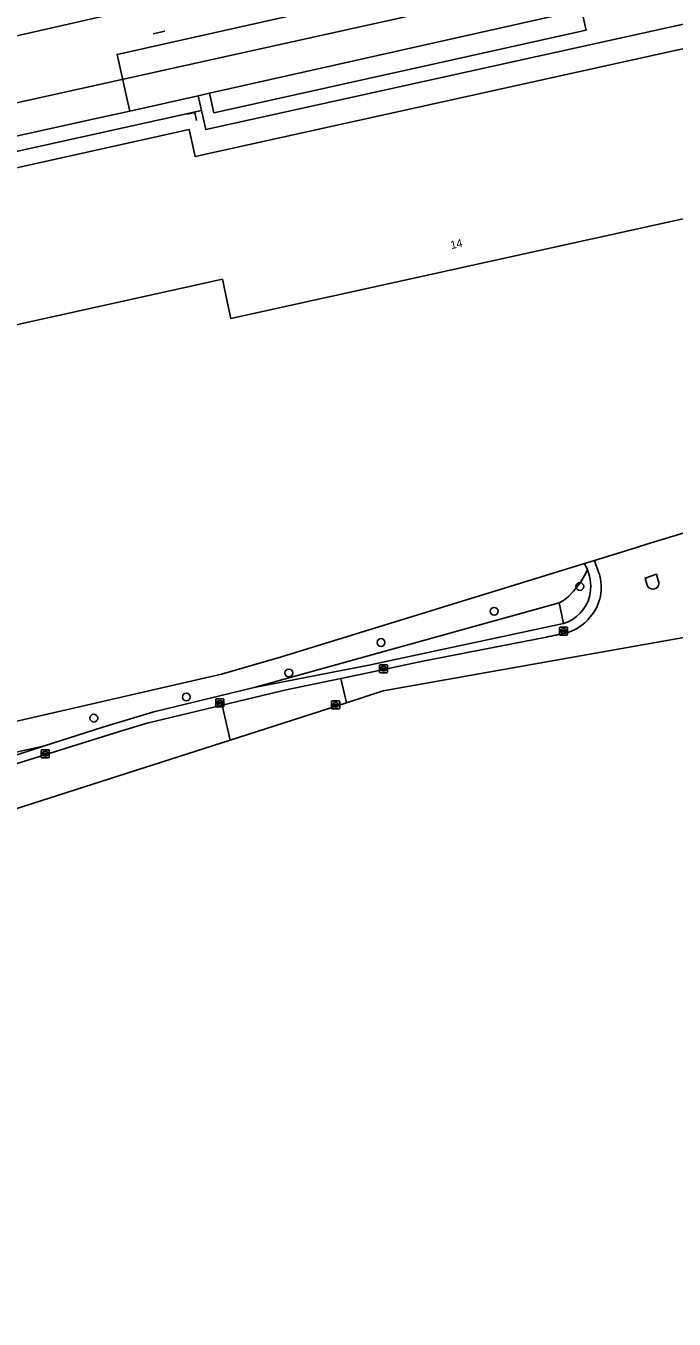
# Model space of a CAD drawing. Extents: x 161477 to 163040, y 383680 to 384871.
# Drawn here: x 162229.1 to 162310.1, y 383720.1 to 383881.8 of the extents above; entities that cross this region are included whole.
import ezdxf

# ---------------------------------------------------------------- set-up
doc = ezdxf.new("R2010")
doc.units = 0
for name, color, linetype in [('IMGEO_Boom', 7, 'Continuous'), ('IMGEO_Erf', 7, 'Continuous'), ('IMGEO_Groenvoorziening', 7, 'Continuous'), ('IMGEO_Hek', 7, 'Continuous'), ('IMGEO_Kolk', 7, 'Continuous'), ('IMGEO_Muur', 7, 'Continuous'), ('IMGEO_Overkapping', 7, 'Continuous'), ('IMGEO_Pand', 7, 'Continuous'), ('IMGEO_Pand_nummerreeks', 7, 'Continuous'), ('IMGEO_Rijbaan_lokaal_open', 7, 'Continuous'), ('IMGEO_Rioolput', 7, 'Continuous'), ('IMGEO_Spoor', 7, 'Continuous'), ('IMGEO_Spoorbaan_halfverhard', 7, 'Continuous'), ('IMGEO_Terreindeel_gesloten', 7, 'Continuous'), ('IMGEO_Terreindeel_halfverhard', 7, 'Continuous'), ('IMGEO_Verkeerseiland_gesloten', 7, 'Continuous'), ('IMGEO_Voetpad_open', 7, 'Continuous')]:
    doc.layers.add(name, color=color, linetype=linetype)

msp = doc.modelspace()

# ---------------------------------------------------------------- linework, layer by layer
at = {"layer": 'IMGEO_Boom'}
for centre in [(162298.35, 383811.69), (162287.64, 383808.59), (162273.51, 383804.69), (162261.99, 383800.88), (162249.18, 383797.87), (162237.62, 383795.23)]:
    msp.add_circle(centre, 0.489, dxfattribs=at)
at = {"layer": 'IMGEO_Erf'}
for points in [[(162421.56, 383883.57), (162312.05, 383859.38), (162312.37, 383857.91), (162254.76, 383845.19), (162254.46, 383846.53), (162253.68, 383850.09), (162222.78, 383843.26)], [(161913.96, 383727.2), (162034.23, 383752.62), (162061.02, 383757.62), (162072.88, 383760.06), (162200.21, 383788.99), (162215.71, 383792.24), (162226.94, 383794.59), (162253.58, 383800.74), (162261.09, 383802.89), (162298.92, 383814.56), (162300.16, 383814.95), (162305.42, 383816.57), (162306.83, 383817), (162311.78, 383818.53), (162312.56, 383818.77), (162312.8, 383817.2), (162313.95, 383815.04), (162315.67, 383812.77), (162316.14, 383812.14)]]:
    msp.add_lwpolyline(points, dxfattribs=at)
at = {"layer": 'IMGEO_Groenvoorziening'}
for points in [[(162298.92, 383814.56), (162261.09, 383802.89), (162253.58, 383800.74), (162226.94, 383794.59), (162215.71, 383792.24), (162200.21, 383788.99), (162072.88, 383760.06), (162061.02, 383757.62), (162034.23, 383752.62), (161913.96, 383727.2)], [(162216.7, 383788.57), (162231.35, 383791.72), (162238.76, 383794.1), (162245.14, 383796.02), (162257.67, 383799.06), (162295.76, 383809.64), (162296.29, 383809.94), (162296.93, 383810.45), (162297.55, 383811.11), (162298.41, 383812.2), (162298.92, 383813.07), (162299.3, 383813.78)], [(162299.3, 383813.78), (162298.92, 383813.07), (162298.41, 383812.2), (162297.55, 383811.11), (162296.93, 383810.45), (162296.29, 383809.94), (162295.76, 383809.64), (162296.32, 383807.07)], [(162007.91, 383740.73), (162033.22, 383746.19), (162060.49, 383752.12), (162097.3, 383759.98), (162118.07, 383764.45), (162141.54, 383769.48), (162180.49, 383777.87), (162190.22, 383779.97), (162198.07, 383781.8), (162206.11, 383783.95), (162214.63, 383786.44), (162216.75, 383787.01), (162217.08, 383787.12), (162231.35, 383791.72), (162216.7, 383788.57), (162197.76, 383783.49), (162191.42, 383781.95), (162037.84, 383749.41), (161933.79, 383726.48)]]:
    msp.add_lwpolyline(points, dxfattribs=at)
msp.add_lwpolyline([(162295.76, 383809.64), (162257.67, 383799.06), (162272.19, 383801.91), (162296.32, 383807.07)], close=True, dxfattribs=at)
for centre, radius, start, end in [((162293.81, 383811.61), 5.89, 21.5643, 30.0357), ((162293.93, 383811.67), 5.77, 347.7831, 21.4277), ((162294.88, 383811.7), 4.85, 287.2964, 345.1082)]:
    msp.add_arc(centre, radius, start, end, dxfattribs=at)
at = {"layer": 'IMGEO_Hek'}
for points in [[(162245.02, 383880.76), (162246.5, 383881.08)], [(162215.71, 383792.24), (162226.94, 383794.59), (162253.58, 383800.74), (162261.09, 383802.89), (162298.92, 383814.56)]]:
    msp.add_lwpolyline(points, dxfattribs=at)
at = {"layer": 'IMGEO_Kolk'}
for p, q in [((162295.82, 383805.68), (162295.82, 383806.54)), ((162295.9, 383806.61), (162296.75, 383806.61)), ((162296.08, 383806.1), (162296.08, 383806.12)), ((162296.52, 383806.07), (162296.12, 383806.07)), ((162296.13, 383806.15), (162296.52, 383806.15)), ((162296.31, 383806.39), (162296.34, 383806.39)), ((162296.57, 383806.12), (162296.57, 383806.1)), ((162296.82, 383806.54), (162296.82, 383805.68)), ((162296.75, 383805.61), (162295.9, 383805.61)), ((162296.33, 383805.83), (162296.31, 383805.83)), ((162273.3, 383800.99), (162273.3, 383801.84)), ((162273.38, 383801.91), (162274.23, 383801.91)), ((162273.56, 383801.41), (162273.56, 383801.42)), ((162273.6, 383801.46), (162274, 383801.46)), ((162274, 383801.37), (162273.6, 383801.37)), ((162273.79, 383801.69), (162273.81, 383801.69)), ((162273.81, 383801.13), (162273.79, 383801.13)), ((162274.04, 383801.42), (162274.04, 383801.41)), ((162274.3, 383801.84), (162274.3, 383800.99)), ((162274.23, 383800.91), (162273.38, 383800.91)), ((162252.86, 383796.71), (162252.86, 383797.56)), ((162252.93, 383797.64), (162253.79, 383797.64)), ((162253.79, 383796.64), (162252.93, 383796.64)), ((162253.12, 383797.13), (162253.12, 383797.14)), ((162253.16, 383797.18), (162253.56, 383797.18)), ((162253.56, 383797.09), (162253.16, 383797.09)), ((162253.35, 383797.42), (162253.37, 383797.42)), ((162253.37, 383796.86), (162253.35, 383796.86)), ((162253.6, 383797.14), (162253.6, 383797.13)), ((162253.86, 383797.56), (162253.86, 383796.71)), ((162231.06, 383790.36), (162231.06, 383791.21)), ((162231.13, 383791.29), (162231.98, 383791.29)), ((162231.98, 383790.28), (162231.13, 383790.28)), ((162231.31, 383790.78), (162231.31, 383790.79)), ((162231.75, 383790.74), (162231.35, 383790.74)), ((162231.36, 383790.83), (162231.75, 383790.83)), ((162231.54, 383791.06), (162231.57, 383791.06)), ((162231.57, 383790.51), (162231.54, 383790.51)), ((162231.8, 383790.79), (162231.8, 383790.78)), ((162232.06, 383791.21), (162232.06, 383790.36))]:
    msp.add_line(p, q, dxfattribs=at)
for points in [[(162295.82, 383805.68), (162295.82, 383806.54)], [(162295.9, 383806.61), (162296.75, 383806.61)], [(162296.82, 383806.54), (162296.82, 383805.68)], [(162296.75, 383805.61), (162295.9, 383805.61)], [(162273.3, 383800.99), (162273.3, 383801.84)], [(162273.38, 383801.91), (162274.23, 383801.91)], [(162274.3, 383801.84), (162274.3, 383800.99)], [(162274.23, 383800.91), (162273.38, 383800.91)], [(162252.86, 383796.71), (162252.86, 383797.56)], [(162252.93, 383797.64), (162253.79, 383797.64)], [(162253.79, 383796.64), (162252.93, 383796.64)], [(162253.86, 383797.56), (162253.86, 383796.71)], [(162231.06, 383790.36), (162231.06, 383791.21)], [(162231.13, 383791.29), (162231.98, 383791.29)], [(162231.98, 383790.28), (162231.13, 383790.28)], [(162232.06, 383791.21), (162232.06, 383790.36)]]:
    msp.add_lwpolyline(points, dxfattribs=at)
for centre, radius, start, end in [((162295.9, 383806.53), 0.0765, 91.552, 178.448), ((162295.9, 383806.53), 0.0765, 91.552, 178.448), ((162296.12, 383806.11), 0.0403, 85.8775, 175.7526), ((162296.12, 383806.1), 0.0366, 178.938, 274.7102), ((162296.53, 383806.11), 0.0386, 1.7309, 96.639), ((162296.52, 383806.11), 0.043, 264.8664, 352.4533), ((162296.75, 383806.53), 0.0765, 1.552, 88.448), ((162296.75, 383806.53), 0.0765, 1.552, 88.448), ((162295.9, 383805.69), 0.0765, 181.552, 268.448), ((162295.9, 383805.69), 0.0765, 181.552, 268.448), ((162296.75, 383805.69), 0.0765, 271.552, 358.448), ((162296.75, 383805.69), 0.0765, 271.552, 358.448), ((162273.38, 383801.84), 0.0765, 91.552, 178.448), ((162273.38, 383801.84), 0.0765, 91.552, 178.448), ((162273.6, 383801.42), 0.0403, 85.8775, 175.7526), ((162273.6, 383801.41), 0.0366, 178.938, 274.7102), ((162274.01, 383801.42), 0.0386, 1.7309, 96.639), ((162274, 383801.41), 0.043, 264.8664, 352.4533), ((162274.23, 383801.84), 0.0765, 1.552, 88.448), ((162274.23, 383801.84), 0.0765, 1.552, 88.448), ((162273.38, 383800.99), 0.0765, 181.552, 268.448), ((162273.38, 383800.99), 0.0765, 181.552, 268.448), ((162274.23, 383800.99), 0.0765, 271.552, 358.448), ((162274.23, 383800.99), 0.0765, 271.552, 358.448), ((162252.94, 383797.56), 0.0765, 91.552, 178.448), ((162252.94, 383797.56), 0.0765, 91.552, 178.448), ((162252.94, 383796.71), 0.0765, 181.552, 268.448), ((162252.94, 383796.71), 0.0765, 181.552, 268.448), ((162253.16, 383797.14), 0.0403, 85.8775, 175.7526), ((162253.16, 383797.13), 0.0366, 178.938, 274.7102), ((162253.56, 383797.14), 0.0386, 1.7309, 96.639), ((162253.56, 383797.14), 0.043, 264.8664, 352.4533), ((162253.78, 383797.56), 0.0765, 1.552, 88.448), ((162253.78, 383797.56), 0.0765, 1.552, 88.448), ((162253.78, 383796.71), 0.0765, 271.552, 358.448), ((162253.78, 383796.71), 0.0765, 271.552, 358.448), ((162231.13, 383791.21), 0.0765, 91.552, 178.448), ((162231.13, 383791.21), 0.0765, 91.552, 178.448), ((162231.13, 383790.36), 0.0765, 181.552, 268.448), ((162231.13, 383790.36), 0.0765, 181.552, 268.448), ((162231.35, 383790.79), 0.0403, 85.8775, 175.7526), ((162231.35, 383790.78), 0.0366, 178.938, 274.7102), ((162231.76, 383790.79), 0.0386, 1.7309, 96.639), ((162231.76, 383790.78), 0.043, 264.8664, 352.4533), ((162231.98, 383791.21), 0.0765, 1.552, 88.448), ((162231.98, 383791.21), 0.0765, 1.552, 88.448), ((162231.98, 383790.36), 0.0765, 271.552, 358.448), ((162231.98, 383790.36), 0.0765, 271.552, 358.448)]:
    msp.add_arc(centre, radius, start, end, dxfattribs=at)
for centre, major_axis, ratio, start_param, end_param in [((162296.31, 383806.11), (-0.387, 0.002), 0.722429, 4.712389, 7.853982), ((162296.33, 383806.11), (-0.39, 0.002), 0.717154, 1.570796, 4.712389), ((162273.79, 383801.41), (-0.387, 0.002), 0.722429, 4.712389, 7.853982), ((162273.81, 383801.41), (-0.39, 0.002), 0.717154, 1.570796, 4.712389), ((162253.35, 383797.14), (-0.387, 0.002), 0.722429, 4.712389, 7.853982), ((162253.37, 383797.14), (-0.39, 0.002), 0.717154, 1.570796, 4.712389), ((162231.54, 383790.78), (-0.387, 0.002), 0.722429, 4.712389, 7.853982), ((162231.57, 383790.78), (-0.39, 0.002), 0.717154, 1.570796, 4.712389)]:
    msp.add_ellipse(centre, major_axis=major_axis, ratio=ratio, start_param=start_param, end_param=end_param, dxfattribs=at)
at = {"layer": 'IMGEO_Muur'}
msp.add_lwpolyline([(162250.45, 383869.94), (162250.26, 383870.94), (162249.33, 383870.73)], dxfattribs=at)
at = {"layer": 'IMGEO_Overkapping'}
msp.add_lwpolyline([(162241.88, 383872.17), (162242.12, 383871.1), (162250.66, 383873.01), (162252.07, 383873.33), (162252.62, 383870.89), (162299.13, 383881.24), (162298.57, 383883.75), (162305.03, 383885.2), (162304.74, 383886.34), (162304.48, 383887.4), (162303.54, 383891.16), (162303.26, 383892.26), (162240.52, 383878.19)], close=True, dxfattribs=at)
at = {"layer": 'IMGEO_Pand'}
msp.add_lwpolyline([(162304.96, 383877.5), (162250.29, 383865.42), (162249.55, 383868.79), (162223.78, 383863.1), (162218.56, 383861.94), (162222.78, 383843.26), (162253.68, 383850.09), (162254.46, 383846.53), (162254.76, 383845.19), (162312.37, 383857.91), (162312.05, 383859.38), (162421.56, 383883.57), (162417.41, 383902.34), (162405.62, 383899.74), (162402.4, 383899.03)], close=True, dxfattribs=at)
at = {"layer": 'IMGEO_Rijbaan_lokaal_open'}
for points in [[(162315.33, 383812.15), (162314.66, 383813.15), (162313.68, 383814.54), (162312.55, 383816.49), (162312.22, 383817.18), (162311.78, 383818.53), (162306.83, 383817), (162305.42, 383816.57), (162300.16, 383814.95), (162300.74, 383813.35)], [(162306.71, 383811.97), (162306.49, 383812.75), (162307.92, 383813.21), (162308.15, 383812.42)], [(162296.37, 383805.82), (162296.01, 383805.74), (162295.7, 383805.68), (162295.4, 383805.62), (162295.09, 383805.56), (162294.79, 383805.49), (162294.48, 383805.43), (162294.18, 383805.37), (162278.73, 383802.34), (162270.9, 383800.71), (162268.48, 383800.21), (162269.21, 383797.16), (162273.78, 383798.63), (162324.96, 383807.75)], [(162254.66, 383792.5), (162269.21, 383797.16), (162268.48, 383800.21), (162261.67, 383798.79), (162253.66, 383796.86), (162254.66, 383792.5)], [(161951.21, 383720.12), (162050.78, 383741.89), (162225.64, 383783.2), (162254.66, 383792.5), (162253.66, 383796.86), (162244.29, 383794.61), (162240.84, 383793.55), (162224.8, 383788.56), (162219.62, 383786.85), (162219.33, 383786.78), (162214.48, 383785.25), (162201.98, 383781.65), (162200.19, 383781.17), (162199.34, 383780.94), (162193.85, 383779.62), (162173.23, 383775.14), (162160.65, 383772.41), (162129.52, 383765.69), (162103.41, 383760.08), (162086.49, 383756.59), (162061.51, 383751.2), (162055.16, 383749.81), (162038.61, 383746.29), (162000, 383738.01)]]:
    msp.add_lwpolyline(points, dxfattribs=at)
for centre, radius, start, end in [((162295.45, 383811.59), 5.58, 318.7426, 18.4435), ((162307.46, 383812.11), 0.759, 190.181, 24.5952), ((162295.24, 383811.21), 5.51, 281.859, 323.1128)]:
    msp.add_arc(centre, radius, start, end, dxfattribs=at)
at = {"layer": 'IMGEO_Rioolput'}
for p, q in [((162267.33, 383796.47), (162267.33, 383797.32)), ((162267.41, 383797.4), (162268.26, 383797.4)), ((162268.26, 383796.4), (162267.41, 383796.4)), ((162267.59, 383796.89), (162267.59, 383796.9)), ((162268.03, 383796.85), (162267.63, 383796.85)), ((162267.64, 383796.94), (162268.03, 383796.94)), ((162267.82, 383797.18), (162267.85, 383797.18)), ((162267.84, 383796.62), (162267.82, 383796.62)), ((162268.08, 383796.9), (162268.08, 383796.89)), ((162268.34, 383797.32), (162268.34, 383796.47))]:
    msp.add_line(p, q, dxfattribs=at)
for points in [[(162267.33, 383796.47), (162267.33, 383797.32)], [(162267.41, 383797.4), (162268.26, 383797.4)], [(162268.26, 383796.4), (162267.41, 383796.4)], [(162268.34, 383797.32), (162268.34, 383796.47)]]:
    msp.add_lwpolyline(points, dxfattribs=at)
for centre, radius, start, end in [((162267.41, 383797.32), 0.0765, 91.552, 178.448), ((162267.41, 383797.32), 0.0765, 91.552, 178.448), ((162267.41, 383796.47), 0.0765, 181.552, 268.448), ((162267.41, 383796.47), 0.0765, 181.552, 268.448), ((162267.63, 383796.9), 0.0403, 85.8775, 175.7526), ((162267.63, 383796.89), 0.0366, 178.938, 274.7102), ((162268.04, 383796.9), 0.0386, 1.7309, 96.639), ((162268.03, 383796.9), 0.043, 264.8664, 352.4533), ((162268.26, 383797.32), 0.0765, 1.552, 88.448), ((162268.26, 383797.32), 0.0765, 1.552, 88.448), ((162268.26, 383796.47), 0.0765, 271.552, 358.448), ((162268.26, 383796.47), 0.0765, 271.552, 358.448)]:
    msp.add_arc(centre, radius, start, end, dxfattribs=at)
for centre, major_axis, ratio, start_param, end_param in [((162267.82, 383796.9), (-0.387, 0.002), 0.722429, 4.712389, 7.853982), ((162267.85, 383796.9), (-0.39, 0.002), 0.717154, 1.570796, 4.712389)]:
    msp.add_ellipse(centre, major_axis=major_axis, ratio=ratio, start_param=start_param, end_param=end_param, dxfattribs=at)
at = {"layer": 'IMGEO_Spoor'}
for points in [[(161754.68, 383774.37), (161849.16, 383795.44), (161951.91, 383818.25), (162017.67, 383832.92), (162036.57, 383837.16), (162110.8, 383854.02), (162201.33, 383874.48), (162299.92, 383896.88), (162339.11, 383905.77), (162371.6, 383913.13), (162387.02, 383916.6), (162393.33, 383917.81), (162399.33, 383918.84), (162404.24, 383919.61), (162409.95, 383920.31), (162415.59, 383920.88), (162421.26, 383921.34), (162428.5, 383921.74), (162433.31, 383921.88), (162439.75, 383921.91), (162444.26, 383921.83)], [(161756.53, 383768.76), (161838.28, 383786.93), (161975.14, 383817.36), (162056.37, 383835.44), (162106.4, 383846.65), (162114.63, 383848.32), (162125.79, 383850.6), (162135.24, 383852.23), (162143.31, 383853.7), (162150.4, 383855), (162159.12, 383856.88), (162165.31, 383858.26), (162254.85, 383878.09), (162292.54, 383886.49), (162314.34, 383891.26), (162320.37, 383892.65), (162328.36, 383894.6), (162337.4, 383896.88)]]:
    msp.add_lwpolyline(points, dxfattribs=at)
at = {"layer": 'IMGEO_Spoorbaan_halfverhard'}
msp.add_lwpolyline([(162180.98, 383857.59), (162237.71, 383870.13), (162242.12, 383871.1), (162250.66, 383873.01), (162252.07, 383873.33), (162298.57, 383883.75)], dxfattribs=at)
at = {"layer": 'IMGEO_Terreindeel_gesloten'}
msp.add_lwpolyline([(162251.07, 383871.17), (162181.38, 383855.78), (162181.81, 383853.83), (162218.56, 383861.94), (162223.78, 383863.1), (162249.55, 383868.79), (162250.29, 383865.42), (162304.96, 383877.5), (162402.4, 383899.03), (162401.94, 383901.13), (162395.4, 383899.68), (162394.39, 383900.33), (162251.6, 383868.79)], close=True, dxfattribs=at)
msp.add_lwpolyline([(162298.57, 383883.75), (162252.07, 383873.33), (162250.66, 383873.01), (162251.07, 383871.17), (162251.6, 383868.79), (162394.39, 383900.33)], dxfattribs=at)
at = {"layer": 'IMGEO_Terreindeel_halfverhard'}
msp.add_lwpolyline([(162181.38, 383855.78), (162251.07, 383871.17), (162250.66, 383873.01), (162242.12, 383871.1), (162237.71, 383870.13), (162180.98, 383857.59)], dxfattribs=at)
at = {"layer": 'IMGEO_Verkeerseiland_gesloten'}
msp.add_lwpolyline([(162308.15, 383812.42), (162307.92, 383813.21), (162306.49, 383812.75), (162306.71, 383811.97)], dxfattribs=at)
msp.add_arc((162307.46, 383812.11), 0.759, 190.181, 24.5952, dxfattribs=at)
at = {"layer": 'IMGEO_Voetpad_open'}
for points in [[(162300.74, 383813.35), (162300.16, 383814.95), (162298.92, 383814.56)], [(162296.32, 383807.07), (162272.19, 383801.91), (162257.67, 383799.06), (162245.14, 383796.02), (162238.76, 383794.1), (162231.35, 383791.72), (162217.08, 383787.12), (162216.75, 383787.01), (162214.63, 383786.44), (162206.11, 383783.95), (162198.07, 383781.8), (162190.22, 383779.97), (162180.49, 383777.87), (162141.54, 383769.48), (162118.07, 383764.45), (162097.3, 383759.98), (162060.49, 383752.12), (162033.22, 383746.19), (162007.91, 383740.73)], [(162224.8, 383788.56), (162240.84, 383793.55), (162244.29, 383794.61), (162253.66, 383796.86), (162261.67, 383798.79), (162268.48, 383800.21), (162270.9, 383800.71), (162278.73, 383802.34), (162294.18, 383805.37), (162294.48, 383805.43), (162294.79, 383805.49), (162295.09, 383805.56), (162295.4, 383805.62), (162295.7, 383805.68), (162296.01, 383805.74), (162296.37, 383805.82)]]:
    msp.add_lwpolyline(points, dxfattribs=at)
for centre, radius, start, end in [((162293.81, 383811.61), 5.89, 21.5643, 30.0357), ((162293.93, 383811.67), 5.77, 347.7831, 21.4277), ((162295.45, 383811.59), 5.58, 318.7426, 18.4435), ((162294.88, 383811.7), 4.85, 287.2964, 345.1082), ((162295.24, 383811.21), 5.51, 281.859, 323.1128)]:
    msp.add_arc(centre, radius, start, end, dxfattribs=at)

# ---------------------------------------------------------------- texts
at = {"layer": 'IMGEO_Pand_nummerreeks'}
msp.add_text('14', height=1, rotation=12.5019, dxfattribs=at).set_placement((162282.3, 383853.85))

doc.saveas('drawing.dxf')
